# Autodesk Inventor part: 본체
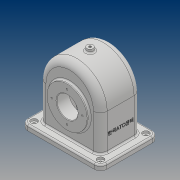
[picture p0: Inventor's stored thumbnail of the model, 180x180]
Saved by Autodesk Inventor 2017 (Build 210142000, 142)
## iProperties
Part Number: 본체
Material: 일반
Document SubType Name: Modeling
Designer: 20
Density: 1 g/cm^3
Appearance: 기본값
Mass: 404.475 g
Surface Area: 1182.21 cm^2
Volume: 404.475 cm^3
Author: 20
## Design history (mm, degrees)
sketch "스케치1"
  geometry: L1 (58, 0)-(58, -78); L2 (58, -78)-(-58, -78); L3 (-58, -78)-(-58, 0); A1 r 58 centre (0, 0) between (58, 0) and (-58, 0); 1 further point
  constraints: 6 end point, 2 point on circle, 2 tangent, 2 vertical, 1 centre point, 1 coincident, 1 horizontal
  dimensions: "d0" = 116 diameter of A1; "d1" = 78 distance from line of L2 point (0, 0)
extrude "돌출1" new body sketch "스케치1" stored distance "d2" = 77; taper "d3" = 0 deg
sketch "스케치3"
  geometry: L1 (52, 5.584)-(52, -85); L2 (52, -85)-(-52, -85); L3 (-52, -85)-(-52, 7.935); A1 r 52 centre (0, 0) between (52, 0) and (-52, 0); 1 further point
  constraints: 6 end point, 2 point on circle, 2 point on line, 2 tangent, 2 vertical, 1 centre point, 1 coincident, 1 horizontal
  dimensions: "d9" = 104 diameter of A1; "d10" = 85 distance from line of L2 point (0, 0)
extrude "돌출3" cut sketch "스케치3" stored distance "d11" = 67; taper "d12" = 0 deg
sketch "스케치4"
  geometry: L1 (133, -93.5)-(-17, -93.5); L2 (-17, -93.5)-(-17, 16.5); L3 (-17, 16.5)-(133, 16.5); L4 (133, 16.5)-(133, -93.5); L5 (133, -93.5)-(-17, 16.5); L6 (-17, -93.5)-(133, 16.5); L7 (0, 0)-(0, -77) reference; L8 (116, -77)-(0, -77) reference; L9 (0, 0)-(116, 0) reference; L10 (116, 0)-(116, -77) reference; 1 further point
  constraints: 12 end point, 2 midpoint, 2 parallel, 1 horizontal, 1 perpendicular
  dimensions: "d13" = 110 distance of L1.end L2.end; "d14" = 150 distance of L2.end L3.end
extrude "돌출4" join sketch "스케치4" distance "d15" = 10; taper "d16" = 0 deg
sketch "스케치5"
  geometry: L1 (-75, -78)-(75, -78) reference; C1 r 38 at (0, -13); 1 further point
  constraints: 1 centre point, 1 vertical alignment
  dimensions: "d17" = 76 diameter of C1; "d18" = 65 distance from line of C1.centre L1
extrude "돌출5" join sketch "스케치5" distance "d19" = 5; taper "d20" = 0 deg
sketch "스케치6"
  geometry: 1 further point
sketch "스케치7"
  geometry: L1 (75, 78)-(-75, 78) reference; C1 r 38 at (0, 13); 1 further point
  constraints: 1 centre point, 1 vertical alignment
  dimensions: "d21" = 76 diameter of C1; "d22" = 65 distance from line of L1 C1.centre
extrude "돌출6" join sketch "스케치7" distance "d23" = 10; taper "d24" = 0 deg
sketch "스케치8"
  geometry: C1 r 38 at (0, 13) reference; C2 r 28 at (0, 13); 1 further point
  constraints: 1 centre point, 1 coincident
  dimensions: "d25" = 56 diameter of C2
extrude "돌출7" join sketch "스케치8" distance "d26" = 14; taper "d27" = 0 deg
sketch "스케치9"
  geometry: C1 r 38 at (0, 0) reference; C2 r 20 at (0, 0); 1 further point
  constraints: 1 centre point, 1 coincident
  dimensions: "d28" = 40 diameter of C2
extrude "돌출8" cut sketch "스케치9" stored distance "d29" = 14; taper "d30" = 0 deg
node "작업 평면1"
sketch "스케치10"
  geometry: L1 (150, 0)-(0, 0) reference; L2 (150, 110)-(150, 0) reference; C1 r 6 at (75, 55); 1 further point
  constraints: 1 centre point
  dimensions: "d32" = 12 diameter of C1; "d33" = 55 distance from line of L1 C1.centre; "d34" = 75 distance from line of C1.centre L2
extrude "돌출9" join sketch "스케치10" stored distance "d35" = 14; taper "d36" = 5 deg
fillet "모깎기1" dims "d37" = 8
fillet "모깎기2" dims "d38" = 13
feature "면 기울기1" dims angle "d39" = 40 deg
fillet "모깎기3" dims "d40" = 12
sketch "스케치12"
  geometry: L1 (78, -17.5)-(78, 68.5) reference; L2 (0, -13)-(68, -13) reference; 2 further points
  constraints: 1 other
  dimensions: "d41" = 40 distance from line of L1 point (38, 25.5); "d42" = 38.5 distance from line of point (38, 25.5) L2
feature "엠보싱1" sketch "스케치12" dims "d0" = 116, "d1" = 78, "d13" = 110, "d14" = 150, "d43" = 0.5, "d44" = 0
sketch "스케치13" dims "d45" = 58
  geometry: C1 r 20 at (0, 0) reference; 3 further points
  constraints: 2 vertical alignment, 1 coincident, 2 other
hole "구멍1" sketch "스케치13" at (0, 29) diameter "d46" = 3.242; stored, may be unused: countersink angle "d50" = 90 deg, drill point angle "d52" = 118 deg; dims "d47" = 8, "d48" = 4, "d49" = 2, "d51" = 10
sketch "스케치14" dims "d56" = 58
  geometry: C1 r 38 at (0, 0) reference; 3 further points
  constraints: 2 vertical alignment, 1 coincident, 2 other
hole "구멍2" sketch "스케치14" at (0, -29) diameter "d57" = 3.242; stored, may be unused: countersink angle "d61" = 90 deg, drill point angle "d63" = 118 deg; dims "d58" = 8, "d59" = 4, "d60" = 2, "d62" = 10
hole "구멍3" diameter "d69" = 4.459; stored, may be unused: countersink angle "d73" = 90 deg, drill point angle "d75" = 118 deg; dims "d67" = 10, "d68" = 10, "d70" = 10, "d71" = 4, "d72" = 2, "d74" = 12.8
sketch "스케치16"
  geometry: A1 r 12 centre (5, 4.5) between (17, 4.5) and (5, 16.5) reference; A2 r 12 centre (5, -81.5) between (5, -93.5) and (17, -81.5) reference; A3 r 12 centre (-121, -81.5) between (-133, -81.5) and (-121, -93.5) reference; A4 r 12 centre (-121, 4.5) between (-121, 16.5) and (-133, 4.5) reference; 5 further points
  constraints: 4 coincident
hole "구멍4" sketch "스케치16" at (5, -81.5), (-121, -81.5), (5, 4.5), (-121, 4.5) diameter "d76" = 5; stored, may be unused: countersink angle "d80" = 90 deg, drill point angle "d82" = 118 deg; dims "d77" = 10, "d78" = 12, "d79" = 4, "d81" = 12.8
fillet "모깎기4" dims "d83" = 3
fillet "모깎기5" dims "d84" = 3
fillet "모깎기6" dims "d85" = 3
fillet "모깎기7" dims "d86" = 3
chamfer "모따기1" distance "d87" = 1; stored, may be unused: second distance "d88" = 2, angle "d89" = 45 deg
fillet "모깎기8" dims "d90" = 3
node "솔리드1"
pattern_circular "원형 패턴1" dims angle "d54" = 360 deg
pattern_circular "원형 패턴2" dims angle "d65" = 360 deg
other parameters: "d31" = -142
